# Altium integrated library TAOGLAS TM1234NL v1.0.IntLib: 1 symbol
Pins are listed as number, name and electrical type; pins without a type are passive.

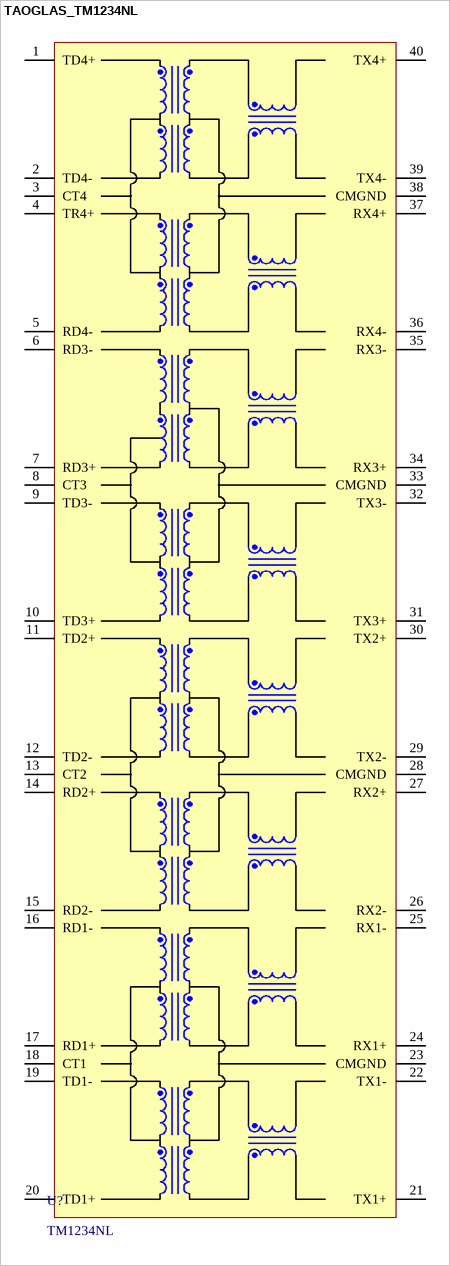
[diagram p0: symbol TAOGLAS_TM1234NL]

## TAOGLAS_TM1234NL
designator U?, comment TM1234NL
LAN 10/100 Base-T transformer Quad Port and 40pin SMT; ComponentLibStatus: Created; MFG: Taoglas; Temp_High: +85C; Temp_Low: -40C
footprint TAOGLAS_TM1234NL (LAN 10/100 Base-T transformer Quad Port and 40pin SMT)
pins: 1 TD4+, 2 TD4-, 3 CT4, 4 TR4+, 5 RD4-, 6 RD3-, 7 RD3+, 8 CT3, 9 TD3-, 10 TD3+, 11 TD2+, 12 TD2-, 13 CT2, 14 RD2+, 15 RD2-, 16 RD1-, 17 RD1+, 18 CT1, 19 TD1-, 20 TD1+, 21 TX1+, 22 TX1-, 23 CMGND, 24 RX1+, 25 RX1-, 26 RX2-, 27 RX2+, 28 CMGND, 29 TX2-, 30 TX2+, 31 TX3+, 32 TX3-, 33 CMGND, 34 RX3+, 35 RX3-, 36 RX4-, 37 RX4+, 38 CMGND, 39 TX4-, 40 TX4+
